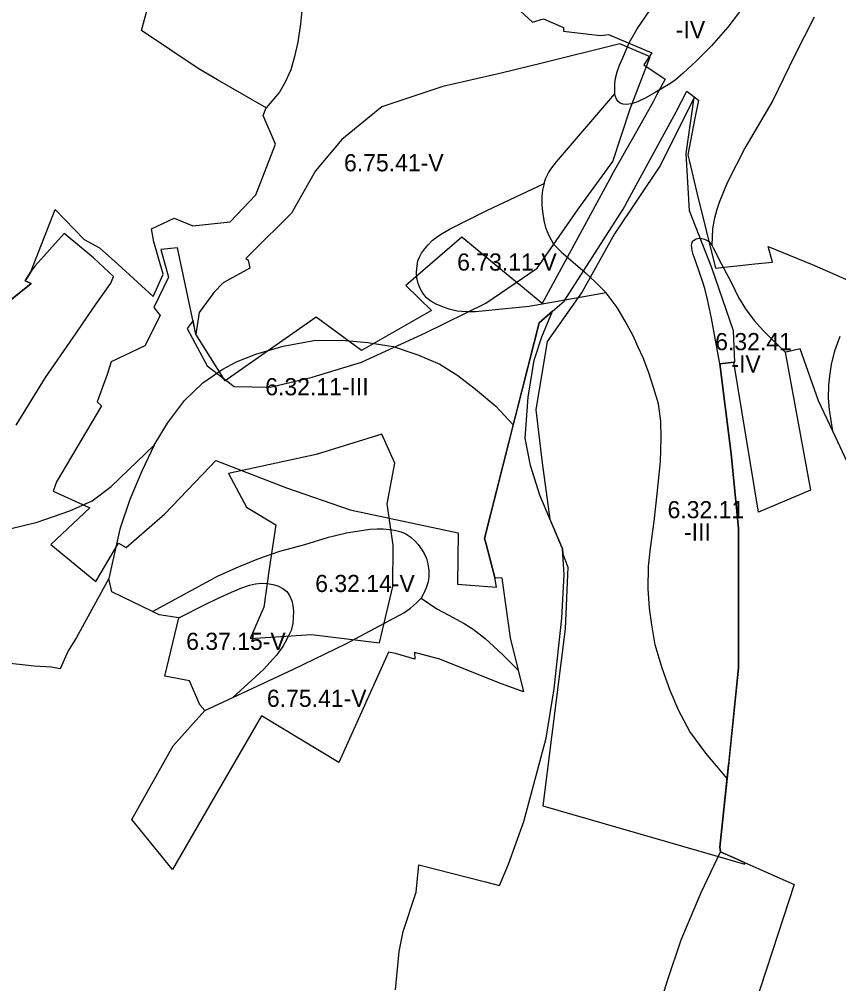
# Model space of a CAD drawing. Extents: x -555156 to -540209, y -1046851 to -1035695.
# Drawn here: x -544645 to -544168, y -1043130 to -1042568 of the extents above; entities that cross this region are included whole.
import ezdxf

# ---------------------------------------------------------------- set-up
doc = ezdxf.new("R2010")
doc.units = 0
for name, color, linetype in [('Vrstva 12', 7, 'Continuous'), ('Vrstva 27', 7, 'Continuous'), ('Vrstva 28', 7, 'Continuous'), ('Vrstva 29', 7, 'Continuous')]:
    doc.layers.add(name, color=color, linetype=linetype)

msp = doc.modelspace()

# ---------------------------------------------------------------- linework, layer by layer
at = {"layer": 'Vrstva 12'}
msp.add_lwpolyline([(-544359.86, -1042556.35), (-544346, -1042569.32), (-544339.58, -1042567.41), (-544327.89, -1042572.5), (-544327.89425, -1042574.627855), (-544313.2, -1042576.31), (-544306.32, -1042577.1), (-544301.7, -1042576.59), (-544276.45, -1042587.33), (-544281.07, -1042594.26), (-544270.43, -1042601.33), (-544268.68, -1042602.49), (-544273.74, -1042611.96), (-544275.79, -1042615.8), (-544287.24, -1042636.09), (-544299.06, -1042657.03), (-544301.2, -1042660.98), (-544340.32, -1042733.24), (-544350.62, -1042724.76), (-544363.41, -1042714.23), (-544387.1, -1042694.72), (-544419.66, -1042722.79), (-544404.853452, -1042737.390525), (-544445.59, -1042760.71), (-544471.97, -1042741.23), (-544525.03, -1042778.41), (-544541.97, -1042751.13), (-544552.64, -1042700.91), (-544562.49, -1042701.89), (-544557.9, -1042717.99), (-544566.44, -1042735.64), (-544562.82, -1042740.19), (-544571.83, -1042758.03), (-544591.38, -1042767.17), (-544593.69, -1042774.71), (-544599.59, -1042790.6), (-544597.05, -1042792.89), (-544623.1, -1042837.12), (-544625.17, -1042842.54), (-544603.74, -1042852.41), (-544626.41, -1042873.63), (-544600.3, -1042895.33), (-544587.06, -1042872.93), (-544582.53, -1042875.46), (-544560.08, -1042855.77), (-544533.95, -1042828.34), (-544530.47, -1042824.69), (-544489.18, -1042840.63), (-544452.12, -1042853.53), (-544389.23, -1042866.95), (-544389.62, -1042896.71), (-544366.918429, -1042898.59966), (-544367.87, -1042892.84), (-544373.03, -1042873.49), (-544373.9, -1042870.22), (-544345.05, -1042755.94), (-544342.19, -1042744.59), (-544334.39, -1042737.84), (-544327.49, -1042731.87), (-544293.26, -1042678.37), (-544284.43, -1042662.15), (-544262.34, -1042621.53), (-544256.13, -1042609.5), (-544249.294591, -1042614.896125), (-544251.56, -1042626.37), (-544255.58, -1042646.72), (-544254.84, -1042649.76), (-544250.19, -1042668.73), (-544239.42, -1042712.68), (-544216.45, -1042710.26), (-544206.25, -1042709.18), (-544208.72, -1042700.03), (-544183.05, -1042710.54), (-544171.15, -1042715.82), (-544151.55, -1042724.51)], dxfattribs=at)
at = {"layer": 'Vrstva 28'}
for points in [[(-544537.69, -1042362.18), (-544537.59, -1042370.27), (-544536.38, -1042379.97), (-544534.08, -1042389.3), (-544531.18, -1042397.05), (-544527.18, -1042405.9), (-544523.43, -1042413.77), (-544518.81, -1042422.36), (-544511.18, -1042436.57), (-544503.97, -1042451.41), (-544496.55, -1042469.23), (-544489.35, -1042488.31), (-544484.9, -1042505.27), (-544481.71, -1042523.06), (-544480.38, -1042540.03), (-544479.89, -1042558.69), (-544481.11, -1042570.32), (-544482.68, -1042580.98), (-544484.5, -1042589.47), (-544486.68, -1042597.1), (-544489.95, -1042604.37), (-544493.34, -1042610.19), (-544501.01, -1042619.24)], [(-544297.98, -1042611.14), (-544298.12, -1042608.51), (-544298.05, -1042605.26), (-544297.57, -1042602), (-544296.6, -1042598.33), (-544295.28, -1042594.45), (-544293.47, -1042590.09), (-544289.72, -1042581.49), (-544284.99, -1042573.25), (-544277.85, -1042562.83), (-544270.58, -1042553.74), (-544259.92, -1042543.2), (-544251.2, -1042535.56), (-544243.09, -1042529.75), (-544235.34, -1042525.27), (-544230.37, -1042523.13)], [(-544501.01, -1042619.24), (-544529.43, -1042602.92), (-544540.77, -1042596.41), (-544573.71, -1042574.3), (-544568.29, -1042554.04), (-544559.11, -1042535.46)], [(-544222.9, -1042560.13), (-544232.22, -1042572.37), (-544241.79, -1042583.15), (-544250.63, -1042592.12), (-544258.28, -1042599.11), (-544263.18, -1042603.27), (-544267.06, -1042605.88), (-544274.61, -1042610.39), (-544280.34, -1042613.59), (-544284.81, -1042615.73), (-544288.29, -1042616.96), (-544291.18, -1042617.35), (-544293.2, -1042617.23), (-544295.01, -1042616.56), (-544296.08, -1042615.69), (-544297.07, -1042614.23), (-544297.62, -1042612.76), (-544297.98, -1042611.14)], [(-544181.87, -1042566.47), (-544193.38, -1042588.93), (-544206.09, -1042615.02), (-544222.41, -1042642.79), (-544232.58, -1042662.94), (-544237.3, -1042674.36), (-544238.61, -1042678.52), (-544240.2, -1042684.33), (-544241.1, -1042689.8), (-544241.64, -1042699.21)], [(-544339.23, -1042663.43), (-544338.4, -1042660.73), (-544336.67, -1042657.2), (-544334.8, -1042654.2), (-544332.07, -1042650.79), (-544297.98, -1042611.14)], [(-544749.41, -1042812.98), (-544728.08, -1042820), (-544696.84, -1042774.37), (-544684.33, -1042761.97), (-544667.45, -1042745.24), (-544637.87, -1042721.66), (-544641.52, -1042719.99), (-544638.13, -1042714.75), (-544623.97, -1042678.49), (-544607.13, -1042696.02), (-544598.1, -1042700.83), (-544587.56, -1042710.42), (-544566.83, -1042729.28), (-544565.67, -1042726.67), (-544561, -1042716.16), (-544566.52, -1042697.26), (-544567.8, -1042689.76), (-544554.69, -1042683.54), (-544543.88, -1042688.11), (-544522.03, -1042685.62), (-544507.06, -1042669.9), (-544495.63, -1042640.4), (-544502.76, -1042623.84), (-544501.01, -1042619.24)], [(-544303, -1042727.1), (-544347.94, -1042735.08), (-544369.44, -1042737.13), (-544379.2, -1042738.1), (-544384.25, -1042738.1), (-544389.79, -1042737.68), (-544394.43, -1042736.64), (-544398.72, -1042735.12), (-544402.11, -1042733.73), (-544405.22, -1042731.93), (-544407.64, -1042729.93), (-544409.79, -1042727.29), (-544411.38, -1042724.59), (-544412.49, -1042721.69), (-544413.32, -1042718.29), (-544413.46, -1042715.11), (-544413.18, -1042711.3), (-544412.7, -1042708.39), (-544411.8, -1042706.31), (-544410.55, -1042703.89), (-544408.89, -1042701.54), (-544407.02, -1042699.25), (-544404.32, -1042696.62), (-544401.35, -1042694.2), (-544398.51, -1042692.4), (-544393.96, -1042689.71), (-544372.65, -1042679.05), (-544339.23, -1042663.43)], [(-544340.06, -1042667.31), (-544340.47, -1042670.91), (-544340.61, -1042676.03), (-544340.2, -1042679.77), (-544339.43, -1042684.96), (-544338.4, -1042688.91), (-544336.53, -1042693.69), (-544333.69, -1042698.67), (-544329.16, -1042703.35), (-544322.38, -1042709.17), (-544315.23, -1042715.23), (-544309.3, -1042720.92), (-544303, -1042727.1)], [(-544339.23, -1042663.43), (-544340.06, -1042667.31)], [(-544236.8, -1042768.46), (-544241.7, -1042741.77), (-544243.99, -1042730.9), (-544245.65, -1042724.46), (-544246.7, -1042720.78), (-544248.57, -1042715.86), (-544251.26, -1042707.9), (-544252.39, -1042704.73), (-544253.03, -1042702.47), (-544253.25, -1042700.84), (-544253.32, -1042699.35), (-544253.25, -1042698.47), (-544252.96, -1042697.59), (-544252.46, -1042696.79), (-544251.69, -1042696.14), (-544250.74, -1042695.66), (-544249.66, -1042695.32), (-544248.48, -1042695.21), (-544247.29, -1042695.35)], [(-544247.29, -1042695.35), (-544245.91, -1042695.75), (-544244.66, -1042696.34), (-544243.35, -1042697.25), (-544242.36, -1042698.29), (-544241.64, -1042699.21)], [(-544241.64, -1042699.21), (-544240.71, -1042700.84), (-544236.11, -1042710.05), (-544229.81, -1042721.56), (-544225.94, -1042729.8), (-544221.94, -1042736.34), (-544216.86, -1042743.25), (-544211.41, -1042749.19), (-544198.93, -1042761.68)], [(-544232.64, -1043010), (-544245.06, -1042995.34), (-544254.39, -1042982.61), (-544260.75, -1042970.53), (-544265.83, -1042958.65), (-544270.5, -1042945.72), (-544274.52, -1042932.15), (-544276.43, -1042920.48), (-544277.91, -1042910.73), (-544278.55, -1042899.49), (-544278.39, -1042886.59), (-544277.33, -1042875.78), (-544275.21, -1042860.3), (-544273.3, -1042844.18), (-544271.4, -1042825.31), (-544270.97, -1042811.53), (-544271.18, -1042801.77), (-544272.67, -1042791.81), (-544275.26, -1042782.72), (-544278.41, -1042773.15), (-544281.56, -1042764.91), (-544284.35, -1042758.73), (-544287.38, -1042752.18), (-544292.1, -1042743.58), (-544296.7, -1042735.58), (-544303, -1042727.1)], [(-544425.75, -1043133.11), (-544423.59, -1043110.76), (-544421.26, -1043099.1), (-544413.77, -1043076.28), (-544412.17, -1043060.3), (-544373.29, -1043070.2), (-544365.14, -1043072.38), (-544360.01, -1043059.94), (-544350.94, -1043035.03), (-544337.93, -1042986.6), (-544333.38, -1042957.77), (-544328.93, -1042916.63), (-544327.52, -1042891.13), (-544328.55, -1042876.12), (-544341.68, -1042844.96), (-544347.17, -1042827.61), (-544350.3, -1042811.66), (-544348.6, -1042787.83), (-544345.08, -1042766.26), (-544340.52, -1042752.66), (-544334.39, -1042737.84), (-544342.19, -1042744.59), (-544345.05, -1042755.94), (-544357.17, -1042803.94)], [(-544171.14, -1042807.57), (-544173.08, -1042795.27), (-544173.56, -1042788.49), (-544173.44, -1042780.85), (-544172.84, -1042775.52), (-544171.94, -1042768.76), (-544170.01, -1042760.88), (-544166.86, -1042752.28)], [(-544566.3, -1042815.86), (-544558.46, -1042802.92), (-544548.71, -1042789.78), (-544537.95, -1042779.49), (-544526.72, -1042771.65), (-544518.03, -1042766.98), (-544507.01, -1042762.74), (-544491.11, -1042758.08), (-544473.31, -1042754.89), (-544456.99, -1042754.68), (-544441.94, -1042755.95)], [(-544441.94, -1042755.95), (-544427.11, -1042758.29), (-544412.7, -1042763.16), (-544399.98, -1042768.68), (-544389.38, -1042775.25), (-544379.21, -1042783.1), (-544367.34, -1042793.06), (-544357.17, -1042803.94)], [(-544198.93, -1042761.68), (-544184.08, -1042842), (-544214.41, -1042854.93), (-544228.7, -1042767.48), (-544236.8, -1042768.46)], [(-544171.14, -1042807.57), (-544179.37, -1042790.05), (-544190.05, -1042759.66), (-544197.42, -1042761.34), (-544198.93, -1042761.68)], [(-544236.8, -1042768.46), (-544230.34, -1042820.79), (-544225.97, -1042864.34), (-544225.94, -1042945.48), (-544232.64, -1043010)], [(-544357.17, -1042803.94), (-544373.9, -1042870.22), (-544373.03, -1042873.49), (-544367.87, -1042892.84), (-544363.89, -1042893.15), (-544363.07, -1042898.92), (-544358.95, -1042927.98), (-544354.34, -1042946.87)], [(-544161.17, -1042828.79), (-544171.14, -1042807.57)], [(-544749.41, -1042812.98), (-544754.57, -1042818.67), (-544763.05, -1042828.63), (-544771.74, -1042839.24), (-544791.66, -1042865.11), (-544756.05, -1042871.05), (-544731.89, -1042873.17), (-544711.55, -1042873.8), (-544697.35, -1042873.38), (-544683.94, -1042872.42), (-544657.66, -1042866.27), (-544634.35, -1042860.76), (-544615.49, -1042853.98), (-544602.35, -1042848.25), (-544591.33, -1042839.98), (-544566.3, -1042815.86)], [(-544566.3, -1042815.86), (-544573.5, -1042830.91), (-544580.5, -1042847.45), (-544586.22, -1042864.84), (-544592.7, -1042893.44)], [(-544567.2, -1042912.73), (-544528.99, -1042891.94), (-544517.13, -1042886.61), (-544505.26, -1042881.88), (-544493.11, -1042877.59), (-544478.58, -1042873.64), (-544464.74, -1042869.42), (-544454.29, -1042866.93), (-544446.88, -1042865.68), (-544440.72, -1042864.71), (-544436.36, -1042864.57), (-544432.97, -1042864.64)], [(-544432.97, -1042864.64), (-544429.24, -1042864.85), (-544426.33, -1042865.27), (-544422.45, -1042866.3), (-544419.83, -1042867.55), (-544416.85, -1042869.49), (-544414.22, -1042871.7), (-544412.49, -1042873.78), (-544410.62, -1042876.45), (-544409.1, -1042879.01), (-544407.78, -1042881.78), (-544406.88, -1042884.97), (-544406.26, -1042888.84), (-544406.26, -1042892.24), (-544406.74, -1042895.42), (-544407.85, -1042898.95), (-544409.51, -1042902.48), (-544410.9, -1042904.98)], [(-544592.7, -1042893.44), (-544611.53, -1042927.81), (-544616.47, -1042935.65), (-544620.97, -1042946.14), (-544626.01, -1042945.16), (-544636.15, -1042944.55), (-544659.01, -1042942.08)], [(-544567.2, -1042912.73), (-544590.9, -1042901.21), (-544592.7, -1042893.44)], [(-544551.89, -1042916.32), (-544536.63, -1042908.71), (-544529.5, -1042905.18), (-544521.2, -1042901.51), (-544515.18, -1042898.88), (-544510.82, -1042897.29), (-544507.36, -1042896.53), (-544503.96, -1042896.25), (-544500.3, -1042896.46)], [(-544500.3, -1042896.46), (-544497.25, -1042897.01), (-544494.28, -1042897.84), (-544491.44, -1042899.37), (-544489.02, -1042901.1), (-544487.49, -1042903.31), (-544486.18, -1042906.43), (-544485.56, -1042909.13), (-544485.21, -1042912.73), (-544485.28, -1042916.12), (-544485.56, -1042919.79), (-544486.52, -1042923.81), (-544488.81, -1042928.45), (-544491.44, -1042933.02), (-544495.04, -1042938.12), (-544502.55, -1042946.49), (-544520.53, -1042962.85)], [(-544520.53, -1042962.85), (-544485.16, -1042946.33), (-544454.64, -1042931.49), (-544420.95, -1042913.46), (-544417.05, -1042910.79), (-544413.46, -1042907.75), (-544410.9, -1042904.98)], [(-544410.9, -1042904.98), (-544401.62, -1042911.07)], [(-544551.89, -1042916.32), (-544563.42, -1042914.57), (-544567.2, -1042912.73)], [(-544401.62, -1042911.07), (-544394.63, -1042914.81), (-544385.77, -1042919.72), (-544380.55, -1042922.94), (-544373.56, -1042928.41), (-544363.66, -1042937.62), (-544354.34, -1042946.87)], [(-544536.85, -1042970.48), (-544539.72, -1042967.08), (-544545.67, -1042953.05), (-544560, -1042950.33), (-544551.89, -1042916.32)], [(-544354.34, -1042946.87), (-544351.25, -1042959.57), (-544365.55, -1042954.37), (-544399.96, -1042940.53), (-544414.76, -1042936.63), (-544414.46, -1042940.52), (-544425.75, -1042937.12), (-544429.82, -1042936.34), (-544458.7, -1043000.67), (-544503.84, -1042973.5), (-544531.13, -1043020.78), (-544555.56, -1043063.11), (-544579.35, -1043033.87), (-544555.25, -1042990.94), (-544536.85, -1042970.48)], [(-544536.85, -1042970.48), (-544520.53, -1042962.85)], [(-544232.64, -1043010), (-544236.8, -1043049.99), (-544236.53, -1043052.82)], [(-544291.69, -1043262.74), (-544287.7, -1043218.32), (-544283.55, -1043186.1), (-544276.35, -1043156.41), (-544267.45, -1043127.78), (-544259.39, -1043104.03), (-544247.74, -1043076.47), (-544236.53, -1043052.82)], [(-544236.53, -1043052.82), (-544193.6, -1043071.8)], [(-544193.6, -1043071.8), (-544209.4, -1043120.02), (-544252.34, -1043251.06), (-544265.75, -1043249.16), (-544267.51, -1043252.69), (-544259.86, -1043257.87), (-544275.24, -1043267.02), (-544291.69, -1043262.74)]]:
    msp.add_lwpolyline(points, dxfattribs=at)
at = {"layer": 'Vrstva 29'}
for points in [[(-544540.178448, -1042738.463125), (-544541.97, -1042751.13), (-544543.662417, -1042743.164377), (-544547.119995, -1042747.830017), (-544535.400024, -1042769.60199), (-544519.682983, -1042781.559021), (-544498.789978, -1042782.028992), (-544474.236023, -1042776.221985), (-544445.575012, -1042767.494019), (-544408.205017, -1042750.421997), (-544373.112, -1042733.130981), (-544343.346985, -1042712.781982), (-544319.393982, -1042678.364014), (-544299.125977, -1042650.47699), (-544289.065002, -1042619.828003), (-544277.508911, -1042589.576904), (-544295.176025, -1042582.02301), (-544341.198975, -1042593.422913), (-544364.210999, -1042599.122986), (-544398.138, -1042606.836975), (-544433.739014, -1042618.724976), (-544456.986023, -1042637.658997), (-544472.268982, -1042656.080994), (-544486.356995, -1042680.736023), (-544509.458984, -1042703.507996), (-544512.85474, -1042707.093504), (-544511.49, -1042708.11), (-544510.63, -1042712.68), (-544526.197705, -1042721.182063), (-544531.596008, -1042726.882019), (-544540.178448, -1042738.463125)], [(-544222.471443, -1043059.0355), (-544236.53, -1043052.82), (-544236.8, -1043049.99), (-544231.811427, -1043001.983023), (-544231.880005, -1043001.588013), (-544231.729135, -1043001.191098), (-544225.94, -1042945.48), (-544225.97, -1042864.34), (-544230.34, -1042820.79), (-544236.8, -1042768.46), (-544228.7, -1042767.48), (-544228.15864, -1042767.414381), (-544228.843018, -1042749.237), (-544241.447998, -1042712.59491), (-544254.617981, -1042679.211975), (-544256.559021, -1042645.883911), (-544251.919983, -1042613.187012), (-544271.497009, -1042652.612), (-544298.278992, -1042692.622986), (-544317.075012, -1042726.513977), (-544337.439026, -1042755.411987), (-544344.039001, -1042795.315002), (-544340.315979, -1042826.007996), (-544335.805456, -1042858.901416), (-544328.55, -1042876.12), (-544328.33971, -1042879.184517), (-544325.411987, -1042886.835022), (-544327.049011, -1042922.878906), (-544339.901978, -1043025.91803), (-544222.351013, -1043059.861023), (-544222.471443, -1043059.0355)], [(-544646.684021, -1042804.072021), (-544629.5, -1042776.398987), (-544611.726013, -1042750.567993), (-544601.911011, -1042735.955994), (-544591.447662, -1042721.362637), (-544590.084267, -1042717.525077), (-544601.680969, -1042706.661011), (-544618.723999, -1042692.536987), (-544635.851013, -1042711.547974), (-544638.012704, -1042714.449637)], [(-544638.012704, -1042714.449637), (-544638.13, -1042714.75), (-544641.52, -1042719.99), (-544637.87, -1042721.66), (-544651.447734, -1042732.48363)], [(-544435.054016, -1042930.89502), (-544427.35498, -1042898.236023), (-544427.098999, -1042874.041016), (-544430.687012, -1042849.989014), (-544426.129028, -1042826.205994), (-544433.726013, -1042809.41803), (-544471.880981, -1042821.315979), (-544522.965027, -1042832.231995), (-544512.572021, -1042851.836975), (-544495.421997, -1042862.146973), (-544499.388, -1042887.77002), (-544502.536987, -1042910.15802), (-544510.409912, -1042928.525024), (-544474.684998, -1042926.080994), (-544435.054016, -1042930.89502)]]:
    msp.add_lwpolyline(points, dxfattribs=at)

# ---------------------------------------------------------------- texts
at = {"layer": 'Vrstva 27'}
for s, p in [('-IV', (-544262.523462, -1042578.75)), ('6.75.41-V', (-544455.731006, -1042656.27)), ('6.73.11-V', (-544389.851006, -1042714.12)), ('6.32.41', (-544239.573394, -1042760.49)), ('-IV', (-544230.143462, -1042773.49)), ('6.32.11-III', (-544501.606548, -1042786.76)), ('6.32.11', (-544267.327261, -1042858.39)), ('-III', (-544257.722769, -1042871.39)), ('6.32.14-V', (-544472.520884, -1042901.37)), ('6.37.15-V', (-544547.666558, -1042935.09)), ('6.75.41-V', (-544500.631006, -1042968.27))]:
    msp.add_text(s, height=10, dxfattribs=at).set_placement(p)

doc.saveas('drawing.dxf')
